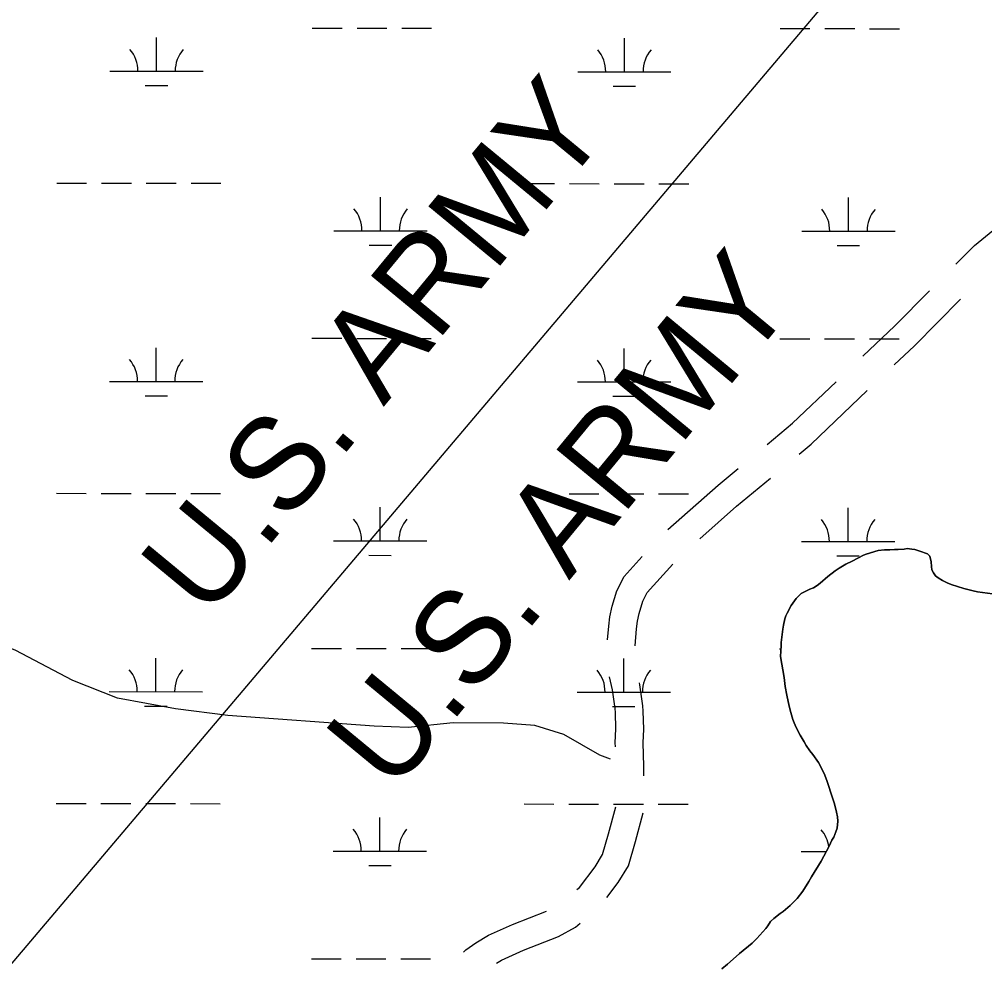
# Model space of a CAD drawing. Extents: x 3148686 to 3186545, y 916144 to 941516.
# Drawn here: x 3153332 to 3154367, y 924474 to 925490 of the extents above; entities that cross this region are included whole.
import ezdxf

# ---------------------------------------------------------------- set-up
doc = ezdxf.new("R2010")
doc.units = 0
for name, color, linetype in [('V-ROAD-CNTR', 7, 'Continuous'), ('V-SITE-VEGE', 7, 'Continuous'), ('V-TOPO-BNDY', 7, 'Continuous'), ('V-TOPO-GNAM-IDEN', 7, 'Continuous'), ('V-TOPO-SHOR', 7, 'Continuous'), ('V-WETL-SWMP', 7, 'Continuous')]:
    doc.layers.add(name, color=color, linetype=linetype)

msp = doc.modelspace()

# ---------------------------------------------------------------- linework, layer by layer
at = {"layer": 'V-ROAD-CNTR'}
for points in [[(3154336.4, 925226.9), (3154356.5, 925247.1), (3154411.8, 925292.1), (3154411.9, 925292.2)], [(3154236.9, 925128.4), (3154271.1, 925161), (3154308.2, 925198.5)], [(3154270.5, 925119.1), (3154292.1, 925139.6), (3154341.5, 925189.5)], [(3154134, 925033.6), (3154161.5, 925056.5), (3154208, 925100.8)], [(3154168.5, 925023.3), (3154181.4, 925034), (3154241.6, 925091.5)], [(3154027.7, 924942.5), (3154081.7, 924990.2), (3154103.2, 925008.1)], [(3154061.8, 924932.6), (3154101.2, 924967.4), (3154137.7, 924997.7)], [(3153963, 924824.1), (3153964.2, 924838.8), (3153965.3, 924848.9), (3153967.8, 924860.3), (3153973, 924876.9), (3153980.6, 924892), (3154000.1, 924913.7)], [(3153992.6, 924817.7), (3153994.1, 924835.9), (3153995, 924844.1), (3153996.8, 924852.6), (3154000.9, 924865.6), (3154005.6, 924874.9), (3154032.8, 924905.2)], [(3153966.2, 924696.4), (3153954.8, 924700.6), (3153915.9, 924722.7), (3153885, 924732.4), (3153851.3, 924734.9), (3153797.2, 924735.1), (3153749.2, 924730.2), (3153712.6, 924731.5), (3153555.7, 924743.1), (3153499.5, 924750.2), (3153437.3, 924761.8), (3153389.5, 924780.6), (3153327.6, 924813.3), (3153254, 924840.2), (3153218.6, 924848.6), (3153190.6, 924852.2), (3153169.4, 924851.3), (3153135.3, 924842.7), (3153096.7, 924826.9), (3153045.7, 924809.9), (3152935.7, 924785.4), (3152933.9, 924785)], [(3153971.3, 924709.5), (3153971.2, 924713.8), (3153971.8, 924728.6), (3153971.3, 924746.3), (3153971, 924750.4), (3153968.2, 924770.6), (3153965, 924784.4)], [(3154002, 924678.5), (3154002, 924688.9), (3154001.2, 924713.6), (3154001.8, 924728.3), (3154001.3, 924747.8), (3154000.8, 924753.6), (3153997.7, 924776), (3153997.2, 924778.2)], [(3153929.9, 924556.3), (3153932.7, 924558.6), (3153949.6, 924580.8), (3153957.6, 924594), (3153964, 924616), (3153971.9, 924645)], [(3153962.3, 924548), (3153974.4, 924563.9), (3153985.3, 924581.8), (3153992.9, 924607.9), (3154001.2, 924638.6)], [(3153808.3, 924489.1), (3153810.9, 924491.8), (3153821.7, 924499.3), (3153835.2, 924507.4), (3153861.1, 924519.1), (3153897.4, 924533.2)], [(3153843.7, 924477.5), (3153849.1, 924480.7), (3153872.7, 924491.4), (3153910.4, 924506.1), (3153928.4, 924516.2), (3153933.6, 924520.5)]]:
    msp.add_lwpolyline(points, dxfattribs=at)
at = {"layer": 'V-SITE-VEGE'}
for p, q in [((3154225.2, 924908.5), (3154237.5, 924914.9)), ((3154237.5, 924914.9), (3154240.4, 924916.1)), ((3154240.4, 924916.1), (3154253.3, 924919.9)), ((3154253.3, 924919.9), (3154259.9, 924920.7)), ((3154259.9, 924920.7), (3154265.6, 924920.9)), ((3154265.6, 924920.9), (3154270.7, 924921.2)), ((3154270.7, 924921.2), (3154274.6, 924921.2)), ((3154274.6, 924921.2), (3154281.2, 924921.6)), ((3154281.2, 924921.6), (3154284.3, 924922)), ((3154284.3, 924922), (3154289.2, 924921.6)), ((3154289.2, 924921.6), (3154292.7, 924921)), ((3154292.7, 924921), (3154298, 924919.4)), ((3154298, 924919.4), (3154306, 924916.6)), ((3154306, 924916.6), (3154308.5, 924914.1)), ((3154211.3, 924901), (3154218.7, 924905.4)), ((3154218.7, 924905.4), (3154225.2, 924908.5)), ((3154308.5, 924914.1), (3154310, 924908)), ((3154310, 924908), (3154310.6, 924902.9)), ((3154199.4, 924892.1), (3154207.2, 924898.3)), ((3154207.2, 924898.3), (3154211.3, 924901)), ((3154310.6, 924902.9), (3154310.8, 924899.4)), ((3154310.8, 924899.4), (3154312.5, 924895.9)), ((3154312.5, 924895.9), (3154314.8, 924893)), ((3154187.8, 924882.5), (3154191.1, 924884.9)), ((3154191.1, 924884.9), (3154199.4, 924892.1)), ((3154314.8, 924893), (3154317.6, 924890.6)), ((3154317.6, 924890.6), (3154322.2, 924887.7)), ((3154322.2, 924887.7), (3154327.3, 924885.3)), ((3154327.3, 924885.3), (3154331.6, 924883.6)), ((3154165.3, 924868.4), (3154170.6, 924873.8)), ((3154170.6, 924873.8), (3154179.8, 924878.7)), ((3154179.8, 924878.7), (3154183.7, 924880)), ((3154183.7, 924880), (3154187.8, 924882.5)), ((3154331.6, 924883.6), (3154345.2, 924879.2)), ((3154345.2, 924879.2), (3154355, 924876.6)), ((3154355, 924876.6), (3154359.8, 924875.6)), ((3154359.8, 924875.6), (3154365.3, 924874.8)), ((3154365.3, 924874.8), (3154375.8, 924873.6)), ((3154159.8, 924861), (3154165.3, 924868.4)), ((3154154.1, 924849.9), (3154155.5, 924852.8)), ((3154155.5, 924852.8), (3154159.8, 924861)), ((3154151.6, 924839.8), (3154153.2, 924846.8)), ((3154153.2, 924846.8), (3154154.1, 924849.9)), ((3154150.4, 924829.8), (3154150.8, 924835.5)), ((3154150.8, 924835.5), (3154151.6, 924839.8)), ((3154149.3, 924821.4), (3154150.4, 924829.8)), ((3154148.5, 924806.4), (3154149.3, 924817.9)), ((3154149.3, 924817.9), (3154149.3, 924821.4)), ((3154152.3, 924783.8), (3154148.5, 924806.4)), ((3154153.5, 924774.2), (3154152.3, 924783.8)), ((3154155.2, 924764.9), (3154153.5, 924774.2)), ((3154157.7, 924753), (3154155.2, 924764.9)), ((3154159.4, 924746.1), (3154157.7, 924753)), ((3154161.7, 924738.9), (3154159.4, 924746.1)), ((3154163.1, 924735.2), (3154161.7, 924738.9)), ((3154165.2, 924730.3), (3154163.1, 924735.2)), ((3154169.6, 924721.9), (3154165.2, 924730.3)), ((3154173.9, 924714.9), (3154169.6, 924721.9)), ((3154176, 924710.9), (3154173.9, 924714.9)), ((3154180.1, 924705.3), (3154176, 924710.9)), ((3154183.2, 924701.4), (3154180.1, 924705.3)), ((3154189.2, 924692.8), (3154183.2, 924701.4)), ((3154195.4, 924681), (3154189.2, 924692.8)), ((3154198.3, 924673.4), (3154195.4, 924681)), ((3154204.5, 924653.7), (3154198.3, 924673.4)), ((3154206.4, 924648.2), (3154204.5, 924653.7)), ((3154208.7, 924639.4), (3154206.4, 924648.2)), ((3154209.5, 924634.5), (3154208.7, 924639.4)), ((3154209.1, 924622.3), (3154209.9, 924629.9)), ((3154209.9, 924629.9), (3154209.5, 924634.5)), ((3154205.5, 924612.7), (3154207.7, 924618.2)), ((3154207.7, 924618.2), (3154209.1, 924622.3)), ((3154200.8, 924603), (3154203.7, 924609.4)), ((3154203.7, 924609.4), (3154205.5, 924612.7)), ((3154192.1, 924587), (3154200.8, 924603)), ((3154181.7, 924570.1), (3154192.1, 924587)), ((3154172.5, 924554.5), (3154179, 924565)), ((3154179, 924565), (3154181.7, 924570.1)), ((3154166.4, 924546.7), (3154172.5, 924554.5)), ((3154159, 924539.2), (3154161.7, 924542.3)), ((3154161.7, 924542.3), (3154166.4, 924546.7)), ((3154148, 924530.6), (3154151.4, 924533)), ((3154151.4, 924533), (3154159, 924539.2)), ((3154134.9, 924517.6), (3154137.9, 924522.3)), ((3154137.9, 924522.3), (3154141.2, 924525.4)), ((3154141.2, 924525.4), (3154148, 924530.6)), ((3154123, 924503.8), (3154132.8, 924514.7)), ((3154132.8, 924514.7), (3154134.9, 924517.6)), ((3154117.9, 924498.9), (3154123, 924503.8)), ((3154104.4, 924487.9), (3154117.9, 924498.9)), ((3154091.5, 924476.4), (3154097.7, 924481.7)), ((3154097.7, 924481.7), (3154104.4, 924487.9)), ((3154085.6, 924471.2), (3154091.5, 924476.4))]:
    msp.add_line(p, q, dxfattribs=at)
at = {"layer": 'V-TOPO-BNDY'}
msp.add_line((3153322.6, 924475.4), (3155483.3, 927026.2), dxfattribs=at)
at = {"layer": 'V-TOPO-SHOR'}
for points in [[(3154375.8, 924873.6), (3154365.3, 924874.8), (3154359.8, 924875.6), (3154355, 924876.6), (3154345.2, 924879.2), (3154331.6, 924883.6), (3154327.3, 924885.3), (3154322.2, 924887.7), (3154317.6, 924890.6), (3154314.8, 924893), (3154312.5, 924895.9), (3154310.8, 924899.4), (3154310.6, 924902.9), (3154310, 924908), (3154308.5, 924914.1), (3154306, 924916.6), (3154298, 924919.4), (3154292.7, 924921), (3154289.2, 924921.6), (3154284.3, 924922), (3154281.2, 924921.6), (3154274.6, 924921.2), (3154270.7, 924921.2), (3154265.6, 924920.9), (3154259.9, 924920.7), (3154253.3, 924919.9), (3154240.4, 924916.1), (3154237.5, 924914.9), (3154225.2, 924908.5), (3154218.7, 924905.4), (3154211.3, 924901), (3154207.2, 924898.3), (3154199.4, 924892.1), (3154191.1, 924884.9), (3154187.8, 924882.5), (3154183.7, 924880), (3154179.8, 924878.7), (3154170.6, 924873.8), (3154165.3, 924868.4), (3154159.8, 924861), (3154155.5, 924852.8), (3154154.1, 924849.9), (3154153.2, 924846.8), (3154151.6, 924839.8), (3154150.8, 924835.5), (3154150.4, 924829.8), (3154149.3, 924821.4), (3154149.3, 924817.9), (3154148.5, 924806.4), (3154152.3, 924783.8), (3154153.5, 924774.2), (3154155.2, 924764.9), (3154157.7, 924753), (3154159.4, 924746.1), (3154161.7, 924738.9), (3154163.1, 924735.2), (3154165.2, 924730.3), (3154169.6, 924721.9), (3154173.9, 924714.9), (3154176, 924710.9), (3154180.1, 924705.3), (3154183.2, 924701.4), (3154189.2, 924692.8), (3154195.4, 924681), (3154198.3, 924673.4), (3154204.5, 924653.7), (3154206.4, 924648.2), (3154208.7, 924639.4), (3154209.5, 924634.5)], [(3154209.5, 924634.5), (3154209.9, 924629.9), (3154209.1, 924622.3), (3154207.7, 924618.2), (3154205.5, 924612.7), (3154203.7, 924609.4), (3154200.8, 924603), (3154192.1, 924587), (3154181.7, 924570.1), (3154179, 924565), (3154172.5, 924554.5), (3154166.4, 924546.7), (3154161.7, 924542.3), (3154159, 924539.2), (3154151.4, 924533), (3154148, 924530.6), (3154141.2, 924525.4), (3154137.9, 924522.3), (3154134.9, 924517.6), (3154132.8, 924514.7), (3154123, 924503.8), (3154117.9, 924498.9), (3154104.4, 924487.9), (3154097.7, 924481.7), (3154091.5, 924476.4), (3154085.6, 924471.2)]]:
    msp.add_lwpolyline(points, dxfattribs=at)
at = {"layer": 'V-WETL-SWMP'}
for p, q in [((3153646.2, 925480.3), (3153678.2, 925480.2)), ((3153694.2, 925480.2), (3153726.2, 925480.2)), ((3153742.2, 925480.2), (3153774.2, 925480.1)), ((3154148.1, 925479.7), (3154180.1, 925479.7)), ((3154196.1, 925479.7), (3154228.1, 925479.7)), ((3154244.1, 925479.6), (3154276.1, 925479.6)), ((3153479.1, 925434), (3153479.2, 925470)), ((3153981, 925433.5), (3153981.1, 925469.5)), ((3153429.1, 925434.1), (3153529.1, 925434)), ((3153931, 925433.5), (3154031, 925433.4)), ((3153467.1, 925418.6), (3153491.1, 925418.6)), ((3153969, 925418.1), (3153993, 925418)), ((3153372.2, 925314.1), (3153404.2, 925314)), ((3153420.2, 925314), (3153452.2, 925314)), ((3153468.2, 925314), (3153500.2, 925313.9)), ((3153516.2, 925313.9), (3153548.2, 925313.9)), ((3153874.1, 925313.5), (3153906.1, 925313.5)), ((3153922.1, 925313.5), (3153954.1, 925313.4)), ((3153970.1, 925313.4), (3154002.1, 925313.4)), ((3154018.1, 925313.4), (3154050.1, 925313.3)), ((3153719.4, 925262.9), (3153719.5, 925298.9)), ((3154221.3, 925262.4), (3154221.4, 925298.4)), ((3153669.4, 925263), (3153769.4, 925262.9)), ((3154171.3, 925262.5), (3154271.3, 925262.4)), ((3153707.4, 925247.5), (3153731.4, 925247.5)), ((3154209.3, 925247), (3154233.3, 925247)), ((3153645.9, 925147.6), (3153677.9, 925147.6)), ((3153693.9, 925147.5), (3153725.9, 925147.5)), ((3153741.9, 925147.5), (3153773.9, 925147.5)), ((3154147.8, 925147.1), (3154179.8, 925147)), ((3154195.8, 925147), (3154227.8, 925147)), ((3154243.8, 925147), (3154275.8, 925146.9)), ((3153478.8, 925101.3), (3153478.8, 925137.3)), ((3153980.7, 925100.8), (3153980.7, 925136.8)), ((3153428.8, 925101.4), (3153528.8, 925101.3)), ((3153930.7, 925100.9), (3154030.7, 925100.8)), ((3153466.8, 925085.9), (3153490.8, 925085.9)), ((3153968.7, 925085.4), (3153992.7, 925085.4)), ((3153371.8, 924981.4), (3153403.8, 924981.3)), ((3153419.8, 924981.3), (3153451.8, 924981.3)), ((3153467.8, 924981.3), (3153499.8, 924981.2)), ((3153515.8, 924981.2), (3153547.8, 924981.2)), ((3153873.7, 924980.9), (3153905.7, 924980.8)), ((3153921.7, 924980.8), (3153953.7, 924980.8)), ((3153969.7, 924980.8), (3154001.7, 924980.7)), ((3154017.7, 924980.7), (3154049.7, 924980.7)), ((3153719.1, 924930.3), (3153719.1, 924966.3)), ((3154221, 924929.7), (3154221, 924965.7)), ((3153669.1, 924930.3), (3153769.1, 924930.2)), ((3154171, 924929.8), (3154271, 924929.7)), ((3153707, 924914.9), (3153731, 924914.8)), ((3154209, 924914.3), (3154233, 924914.3)), ((3153645.5, 924814.9), (3153677.5, 924814.9)), ((3153693.5, 924814.9), (3153725.5, 924814.8)), ((3153741.5, 924814.8), (3153773.5, 924814.8)), ((3154147.4, 924814.4), (3154149.1, 924814.4)), ((3153478.4, 924768.7), (3153478.5, 924804.7)), ((3153980.3, 924768.1), (3153980.4, 924804.1)), ((3153428.4, 924768.7), (3153528.4, 924768.6)), ((3153930.3, 924768.2), (3154030.3, 924768.1)), ((3153466.4, 924753.2), (3153490.4, 924753.2)), ((3153968.3, 924752.7), (3153992.3, 924752.7)), ((3153371.5, 924648.7), (3153403.5, 924648.7)), ((3153419.5, 924648.7), (3153451.5, 924648.6)), ((3153467.5, 924648.6), (3153499.5, 924648.6)), ((3153515.5, 924648.6), (3153547.5, 924648.5)), ((3153873.4, 924648.2), (3153905.4, 924648.1)), ((3153921.4, 924648.1), (3153953.4, 924648.1)), ((3153969.4, 924648.1), (3154001.4, 924648)), ((3154017.4, 924648), (3154049.4, 924648)), ((3153718.7, 924597.6), (3153718.8, 924633.6)), ((3153668.7, 924597.7), (3153768.7, 924597.5)), ((3154170.6, 924597.1), (3154197.6, 924597.1)), ((3153706.7, 924582.2), (3153730.7, 924582.2)), ((3153645.2, 924482.2), (3153677.2, 924482.2)), ((3153693.2, 924482.2), (3153725.2, 924482.2)), ((3153741.2, 924482.1), (3153773.2, 924482.1))]:
    msp.add_line(p, q, dxfattribs=at)
msp.add_lwpolyline([(3154085.6, 924471.2), (3154091.5, 924476.4), (3154097.7, 924481.7), (3154104.4, 924487.9), (3154117.9, 924498.9), (3154123, 924503.8), (3154132.8, 924514.7), (3154134.9, 924517.6), (3154137.9, 924522.3), (3154141.2, 924525.4), (3154148, 924530.6), (3154151.4, 924533), (3154159, 924539.2), (3154161.7, 924542.3), (3154166.4, 924546.7), (3154172.5, 924554.5), (3154179, 924565), (3154181.7, 924570.1), (3154192.1, 924587), (3154200.8, 924603), (3154203.7, 924609.4), (3154205.5, 924612.7), (3154207.7, 924618.2), (3154209.1, 924622.3), (3154209.9, 924629.9), (3154209.5, 924634.5), (3154208.7, 924639.4), (3154206.4, 924648.2), (3154204.5, 924653.7), (3154198.3, 924673.4), (3154195.4, 924681), (3154189.2, 924692.8), (3154183.2, 924701.4), (3154180.1, 924705.3), (3154176, 924710.9), (3154173.9, 924714.9), (3154169.6, 924721.9), (3154165.2, 924730.3), (3154163.1, 924735.2), (3154161.7, 924738.9), (3154159.4, 924746.1), (3154157.7, 924752.9), (3154155.2, 924764.9), (3154153.5, 924774.2), (3154152.3, 924783.8), (3154148.5, 924806.4), (3154149.3, 924817.9), (3154149.3, 924821.4), (3154150.4, 924829.8), (3154150.8, 924835.5), (3154151.6, 924839.8), (3154153.2, 924846.8), (3154154.1, 924849.9), (3154155.5, 924852.8), (3154159.8, 924861), (3154165.3, 924868.4), (3154170.6, 924873.8), (3154179.8, 924878.7), (3154183.7, 924880), (3154187.8, 924882.5), (3154191.1, 924884.9), (3154199.4, 924892.1), (3154207.2, 924898.3), (3154211.3, 924901), (3154218.7, 924905.4), (3154225.2, 924908.5), (3154237.5, 924914.9), (3154240.4, 924916.1), (3154253.3, 924919.9), (3154259.9, 924920.7), (3154265.6, 924920.9), (3154270.7, 924921.2), (3154274.6, 924921.2), (3154281.2, 924921.6), (3154284.3, 924922), (3154289.2, 924921.6), (3154292.7, 924921), (3154298, 924919.4), (3154306, 924916.6), (3154308.5, 924914.1), (3154310, 924908), (3154310.6, 924902.9), (3154310.8, 924899.4), (3154312.5, 924895.9), (3154314.8, 924893), (3154317.6, 924890.6), (3154322.2, 924887.7), (3154327.3, 924885.3), (3154331.6, 924883.6), (3154345.2, 924879.2), (3154355, 924876.6), (3154359.8, 924875.6), (3154365.3, 924874.8), (3154375.8, 924873.6)], dxfattribs=at)
for centre, start, end in [((3153423.9, 925434.5), 359.1678, 40.7115), ((3153534.4, 925434.4), 139.1678, 180.7115), ((3153925.8, 925434), 359.1678, 40.7115), ((3154036.3, 925433.9), 139.1678, 180.7115), ((3153664.2, 925263.5), 359.1678, 40.7115), ((3153774.7, 925263.4), 139.1678, 180.7115), ((3154166.1, 925263), 359.1678, 40.7115), ((3154276.6, 925262.8), 139.1678, 180.7115), ((3153423.5, 925101.9), 359.1678, 40.7115), ((3153534, 925101.8), 139.1678, 180.7115), ((3153925.4, 925101.3), 359.1678, 40.7115), ((3154035.9, 925101.2), 139.1678, 180.7115), ((3153663.8, 924930.8), 359.1678, 40.7115), ((3153774.3, 924930.7), 139.1678, 180.7115), ((3154165.7, 924930.3), 359.1678, 40.7115), ((3154276.2, 924930.2), 139.1678, 180.7115), ((3153423.2, 924769.2), 359.1678, 40.7115), ((3153533.7, 924769.1), 139.1678, 180.7115), ((3153925.1, 924768.7), 359.1678, 40.7115), ((3154035.6, 924768.6), 139.1678, 180.7115), ((3153663.5, 924598.1), 359.1678, 40.7115), ((3153774, 924598), 139.1678, 180.7115), ((3154165.4, 924597.6), 7.4056, 40.7115)]:
    msp.add_arc(centre, 35.2, start, end, dxfattribs=at)

# ---------------------------------------------------------------- texts
at = {"layer": 'V-TOPO-GNAM-IDEN'}
for p in [(3153533.4, 924844.5), (3153732.4, 924658.2)]:
    msp.add_text('U.S. ARMY', height=100, rotation=50.4666, dxfattribs=at).set_placement(p)

doc.saveas('drawing.dxf')
